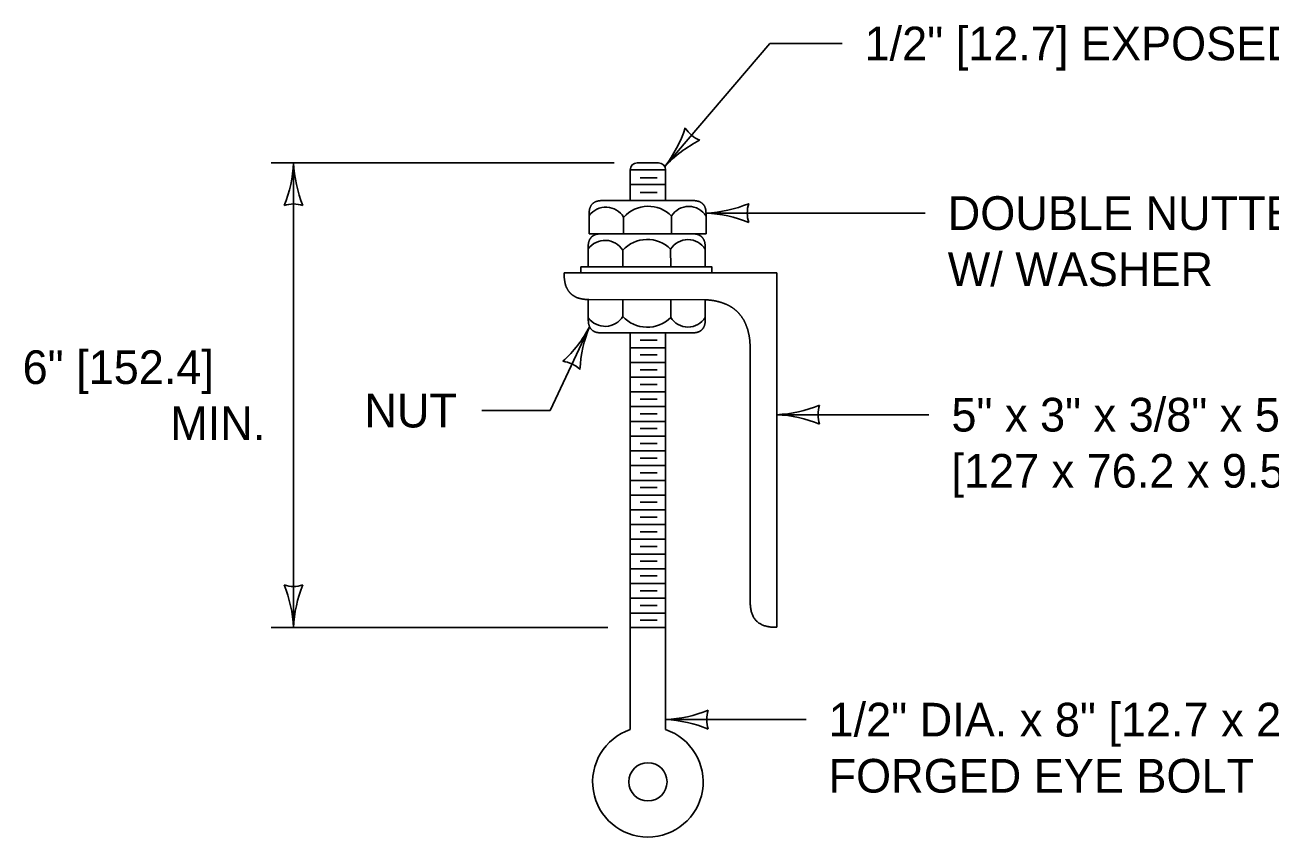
# Model space of a CAD drawing. Extents: x 49991.4 to 50021, y 49987.6 to 50011.4.
# Drawn here: x 50013.253 to 50015.471, y 49992.082 to 49993.529 of the extents above; entities that cross this region are included whole.
import ezdxf

# ---------------------------------------------------------------- set-up
doc = ezdxf.new("R2010")
doc.units = 0
for name, color, linetype in [('Level 1', 7, 'Continuous'), ('Level 2', 7, 'Continuous'), ('Level 3', 7, 'Continuous')]:
    doc.layers.add(name, color=color, linetype=linetype)

msp = doc.modelspace()

# ---------------------------------------------------------------- linework, layer by layer
at = {"layer": 'Level 1'}
for p, q in [((50014.3313, 49993.2711), (50014.3313, 49993.2166)), ((50014.3313, 49993.2711), (50014.3943, 49993.2711)), ((50014.3439, 49993.2837), (50014.3817, 49993.2837)), ((50014.3943, 49993.2711), (50014.3943, 49993.2166)), ((50014.3313, 49993.245), (50014.3943, 49993.245)), ((50014.349, 49993.2573), (50014.379, 49993.2573)), ((50014.349, 49993.2311), (50014.379, 49993.2311)), ((50014.443, 49993.2166), (50014.2815, 49993.2166)), ((50014.2582, 49993.1932), (50014.2582, 49993.1573)), ((50014.3196, 49993.1871), (50014.3196, 49993.1573)), ((50014.4049, 49993.1573), (50014.4049, 49993.189)), ((50014.4664, 49993.1573), (50014.4664, 49993.1932)), ((50014.2582, 49993.1573), (50014.4664, 49993.1573)), ((50014.4414, 49993.1573), (50014.2798, 49993.1573)), ((50014.2566, 49993.134), (50014.2566, 49993.0984)), ((50014.4034, 49993.0984), (50014.4033, 49993.1299)), ((50014.4648, 49993.0984), (50014.4648, 49993.134)), ((50014.318, 49993.1279), (50014.318, 49993.0984)), ((50014.5924, 49993.0875), (50014.2137, 49993.0875)), ((50014.2137, 49993.0875), (50014.2137, 49993.0847)), ((50014.5924, 49992.4563), (50014.5924, 49993.0875)), ((50014.2566, 49993.04), (50014.4649, 49993.0398)), ((50014.2566, 49993.0042), (50014.2566, 49993.04)), ((50014.3181, 49993.0101), (50014.3183, 49993.04)), ((50014.4034, 49993.0399), (50014.4034, 49993.0082)), ((50014.4649, 49993.0398), (50014.4649, 49993.0042)), ((50014.4416, 49992.9806), (50014.28, 49992.9806)), ((50014.3313, 49992.9806), (50014.3313, 49992.274)), ((50014.3313, 49992.9806), (50014.3943, 49992.9806)), ((50014.3943, 49992.9806), (50014.3943, 49992.2741)), ((50014.3313, 49992.9543), (50014.3943, 49992.9543)), ((50014.349, 49992.9678), (50014.379, 49992.9678)), ((50014.349, 49992.9415), (50014.379, 49992.9415)), ((50014.545, 49992.9509), (50014.545, 49992.501)), ((50014.3313, 49992.9282), (50014.3943, 49992.9282)), ((50014.349, 49992.9152), (50014.379, 49992.9152)), ((50014.3313, 49992.9019), (50014.3943, 49992.9019)), ((50014.349, 49992.889), (50014.379, 49992.889)), ((50014.3313, 49992.8756), (50014.3943, 49992.8756)), ((50014.3313, 49992.8494), (50014.3943, 49992.8494)), ((50014.349, 49992.8627), (50014.379, 49992.8627)), ((50014.3313, 49992.8231), (50014.3943, 49992.8231)), ((50014.349, 49992.8365), (50014.379, 49992.8365)), ((50014.3313, 49992.7968), (50014.3943, 49992.7968)), ((50014.349, 49992.8103), (50014.379, 49992.8103)), ((50014.349, 49992.7839), (50014.379, 49992.7839)), ((50014.3313, 49992.7707), (50014.3943, 49992.7707)), ((50014.349, 49992.7577), (50014.379, 49992.7577)), ((50014.3313, 49992.7443), (50014.3943, 49992.7443)), ((50014.349, 49992.7315), (50014.379, 49992.7315)), ((50014.3313, 49992.718), (50014.3943, 49992.718)), ((50014.3313, 49992.6919), (50014.3943, 49992.6919)), ((50014.349, 49992.7052), (50014.379, 49992.7052)), ((50014.3313, 49992.6656), (50014.3943, 49992.6656)), ((50014.349, 49992.6789), (50014.379, 49992.6789)), ((50014.349, 49992.6527), (50014.379, 49992.6527)), ((50014.3313, 49992.6393), (50014.3943, 49992.6393)), ((50014.349, 49992.6264), (50014.379, 49992.6264)), ((50014.3313, 49992.6131), (50014.3943, 49992.6131)), ((50014.349, 49992.6002), (50014.379, 49992.6002)), ((50014.3313, 49992.5868), (50014.3943, 49992.5868)), ((50014.3313, 49992.5605), (50014.3943, 49992.5605)), ((50014.349, 49992.574), (50014.379, 49992.574)), ((50014.3313, 49992.5344), (50014.3943, 49992.5344)), ((50014.349, 49992.5477), (50014.379, 49992.5477)), ((50014.3313, 49992.5081), (50014.3943, 49992.5081)), ((50014.349, 49992.5214), (50014.379, 49992.5214)), ((50014.349, 49992.4952), (50014.379, 49992.4952)), ((50014.3313, 49992.4817), (50014.3943, 49992.4817)), ((50014.349, 49992.4689), (50014.379, 49992.4689)), ((50014.3313, 49992.4556), (50014.3943, 49992.4556)), ((50014.5924, 49992.4563), (50014.5898, 49992.4563))]:
    msp.add_line(p, q, dxfattribs=at)
msp.add_lwpolyline([(50014.4769, 49993.0875), (50014.4769, 49993.0984), (50014.2436, 49993.0984), (50014.2436, 49993.0875)], dxfattribs=at)
msp.add_circle((50014.3628, 49992.1809), 0.0341, dxfattribs=at)
for centre, radius, start, end in [((50014.3439, 49993.2711), 0.0126, 90, 180), ((50014.3817, 49993.2711), 0.0126, 0, 90), ((50014.288, 49993.1679), 0.0369, 31.3232, 143.8567), ((50014.3632, 49993.1477), 0.0587, 44.7321, 137.9001), ((50014.4356, 49993.1698), 0.0362, 31.6559, 147.9066), ((50014.2864, 49993.1087), 0.0369, 31.3232, 143.832), ((50014.3615, 49993.0886), 0.0587, 44.7321, 137.9001), ((50014.434, 49993.1107), 0.0362, 31.6277, 147.9066), ((50014.2866, 49993.0293), 0.0369, 215.7511, 328.6768), ((50014.3617, 49993.0495), 0.0587, 222.0999, 315.2679), ((50014.4341, 49993.0274), 0.0362, 212.0934, 328.1984), ((50014.3628, 49992.1808), 0.0984, 108.672, 71.33)]:
    msp.add_arc(centre, radius, start, end, dxfattribs=at)
for points in [[(50014.2582, 49993.1932), (50014.2582, 49993.1943), (50014.2582, 49993.1956), (50014.2583, 49993.1969), (50014.2584, 49993.198), (50014.2587, 49993.1992), (50014.2588, 49993.2003), (50014.2588, 49993.2013), (50014.2593, 49993.2023), (50014.2596, 49993.2032), (50014.26, 49993.2043), (50014.2603, 49993.2054), (50014.2607, 49993.2061), (50014.2611, 49993.207), (50014.2617, 49993.2078), (50014.2622, 49993.2087), (50014.2627, 49993.2094), (50014.2634, 49993.21), (50014.264, 49993.2106), (50014.2647, 49993.2114), (50014.2654, 49993.2119), (50014.2661, 49993.2124), (50014.2668, 49993.213), (50014.2678, 49993.2135), (50014.2685, 49993.2139), (50014.2694, 49993.2145), (50014.2703, 49993.2147), (50014.2713, 49993.2151), (50014.2723, 49993.2155), (50014.2734, 49993.2156), (50014.2744, 49993.2159), (50014.2756, 49993.2161), (50014.2767, 49993.2162), (50014.2779, 49993.2163), (50014.2791, 49993.2164), (50014.2802, 49993.2166), (50014.2815, 49993.2166)], [(50014.4664, 49993.1932), (50014.4664, 49993.1943), (50014.4662, 49993.1956), (50014.4662, 49993.1969), (50014.4662, 49993.198), (50014.4659, 49993.1992), (50014.4657, 49993.2003), (50014.4655, 49993.2013), (50014.4653, 49993.2023), (50014.4649, 49993.2032), (50014.4646, 49993.2043), (50014.4641, 49993.2054), (50014.4639, 49993.2061), (50014.4634, 49993.207), (50014.4629, 49993.2078), (50014.4623, 49993.2087), (50014.4617, 49993.2094), (50014.4612, 49993.21), (50014.4605, 49993.2106), (50014.4599, 49993.2114), (50014.4592, 49993.2119), (50014.4585, 49993.2124), (50014.4577, 49993.213), (50014.4569, 49993.2135), (50014.456, 49993.2139), (50014.4551, 49993.2145), (50014.4542, 49993.2147), (50014.4532, 49993.2151), (50014.4522, 49993.2155), (50014.4511, 49993.2156), (50014.4501, 49993.2159), (50014.449, 49993.2161), (50014.4478, 49993.2162), (50014.4468, 49993.2163), (50014.4454, 49993.2164), (50014.4442, 49993.2166), (50014.443, 49993.2166)], [(50014.2566, 49993.134), (50014.2566, 49993.1352), (50014.2566, 49993.1364), (50014.2566, 49993.1377), (50014.2567, 49993.1388), (50014.2571, 49993.1399), (50014.2572, 49993.141), (50014.2574, 49993.1422), (50014.2577, 49993.1432), (50014.2579, 49993.1442), (50014.2583, 49993.1453), (50014.2587, 49993.1461), (50014.259, 49993.147), (50014.2596, 49993.1478), (50014.26, 49993.1487), (50014.2606, 49993.1494), (50014.2611, 49993.1502), (50014.2617, 49993.1508), (50014.2625, 49993.1515), (50014.2631, 49993.1522), (50014.2637, 49993.1528), (50014.2645, 49993.1532), (50014.2652, 49993.1538), (50014.2661, 49993.1543), (50014.267, 49993.1548), (50014.2678, 49993.1552), (50014.2688, 49993.1556), (50014.2696, 49993.156), (50014.2708, 49993.1562), (50014.2719, 49993.1566), (50014.2728, 49993.1567), (50014.274, 49993.1569), (50014.2751, 49993.1572), (50014.2762, 49993.1572), (50014.2775, 49993.1573), (50014.2787, 49993.1573), (50014.2798, 49993.1573)], [(50014.4648, 49993.134), (50014.4648, 49993.1352), (50014.4646, 49993.1364), (50014.4646, 49993.1377), (50014.4646, 49993.1388), (50014.4643, 49993.1399), (50014.4641, 49993.141), (50014.4639, 49993.1422), (50014.4637, 49993.1432), (50014.4634, 49993.1442), (50014.463, 49993.1453), (50014.4627, 49993.1461), (50014.4623, 49993.147), (50014.4617, 49993.1478), (50014.4612, 49993.1487), (50014.4607, 49993.1494), (50014.4601, 49993.1502), (50014.4596, 49993.1508), (50014.4589, 49993.1515), (50014.4583, 49993.1522), (50014.4577, 49993.1528), (50014.4569, 49993.1532), (50014.4561, 49993.1538), (50014.4552, 49993.1543), (50014.4544, 49993.1548), (50014.4536, 49993.1552), (50014.4526, 49993.1556), (50014.4516, 49993.156), (50014.4505, 49993.1562), (50014.4495, 49993.1566), (50014.4485, 49993.1567), (50014.4474, 49993.1569), (50014.4463, 49993.1572), (50014.4451, 49993.1572), (50014.4439, 49993.1573), (50014.4427, 49993.1573), (50014.4414, 49993.1573)], [(50014.2566, 49993.0042), (50014.2566, 49993.0029), (50014.2567, 49993.0016), (50014.2569, 49993.0003), (50014.2571, 49992.9992), (50014.2572, 49992.998), (50014.2572, 49992.9969), (50014.2575, 49992.9959), (50014.2578, 49992.995), (50014.2581, 49992.9938), (50014.2585, 49992.9929), (50014.2588, 49992.992), (50014.2593, 49992.9911), (50014.2596, 49992.9903), (50014.2602, 49992.9894), (50014.2608, 49992.9886), (50014.2613, 49992.9878), (50014.2618, 49992.9872), (50014.2626, 49992.9866), (50014.2633, 49992.9859), (50014.2639, 49992.9853), (50014.2646, 49992.9847), (50014.2654, 49992.9842), (50014.2662, 49992.9837), (50014.2672, 49992.9832), (50014.2679, 49992.9829), (50014.2689, 49992.9824), (50014.2699, 49992.9821), (50014.2709, 49992.9818), (50014.2719, 49992.9815), (50014.273, 49992.9814), (50014.2741, 49992.9812), (50014.2752, 49992.9809), (50014.2764, 49992.9809), (50014.2776, 49992.9808), (50014.2788, 49992.9806), (50014.28, 49992.9806)], [(50014.4649, 49993.0042), (50014.4649, 49993.0029), (50014.4648, 49993.0016), (50014.4648, 49993.0003), (50014.4646, 49992.9992), (50014.4646, 49992.998), (50014.4643, 49992.9969), (50014.464, 49992.9959), (50014.4638, 49992.995), (50014.4635, 49992.9938), (50014.4631, 49992.9929), (50014.4628, 49992.992), (50014.4623, 49992.9911), (50014.4619, 49992.9903), (50014.4616, 49992.9894), (50014.4608, 49992.9886), (50014.4602, 49992.9878), (50014.4598, 49992.9872), (50014.4591, 49992.9866), (50014.4585, 49992.9859), (50014.4577, 49992.9853), (50014.457, 49992.9847), (50014.4561, 49992.9842), (50014.4555, 49992.9837), (50014.4546, 49992.9832), (50014.4537, 49992.9829), (50014.4526, 49992.9824), (50014.4518, 49992.9821), (50014.4508, 49992.9818), (50014.4497, 49992.9815), (50014.4486, 49992.9814), (50014.4476, 49992.9812), (50014.4464, 49992.9809), (50014.4453, 49992.9809), (50014.4441, 49992.9808), (50014.4428, 49992.9806), (50014.4416, 49992.9806)], [(50014.545, 49992.501), (50014.5452, 49992.4969), (50014.5455, 49992.4931), (50014.546, 49992.4897), (50014.5466, 49992.4862), (50014.5473, 49992.4829), (50014.5484, 49992.48), (50014.5496, 49992.477), (50014.551, 49992.4743), (50014.5525, 49992.4718), (50014.5542, 49992.4695), (50014.5562, 49992.4674), (50014.5583, 49992.4656), (50014.5606, 49992.4637), (50014.5632, 49992.4623), (50014.5658, 49992.4608), (50014.5687, 49992.4596), (50014.5717, 49992.4586), (50014.575, 49992.4579), (50014.5784, 49992.4572), (50014.5819, 49992.4567), (50014.5857, 49992.4564), (50014.5898, 49992.4563)]]:
    msp.add_spline(points, degree=3, dxfattribs=at)
for points in [[(50014.2137, 49993.0847), (50014.2137, 49993.0834), (50014.2137, 49993.082), (50014.2138, 49993.0807), (50014.2139, 49993.0794), (50014.2139, 49993.0782), (50014.2141, 49993.0769), (50014.2142, 49993.0757), (50014.2144, 49993.0746), (50014.2146, 49993.0734), (50014.2148, 49993.0722), (50014.215, 49993.0711), (50014.2152, 49993.0699), (50014.2153, 49993.0694), (50014.2154, 49993.0688), (50014.2155, 49993.0683), (50014.2156, 49993.068), (50014.2156, 49993.0678), (50014.2157, 49993.0675), (50014.2158, 49993.0672), (50014.2158, 49993.067), (50014.2159, 49993.0667), (50014.216, 49993.0662), (50014.2162, 49993.0657), (50014.2164, 49993.0652), (50014.2166, 49993.0647), (50014.2168, 49993.0642), (50014.217, 49993.0637), (50014.2172, 49993.0632), (50014.2174, 49993.0627), (50014.2176, 49993.0622), (50014.2178, 49993.0618), (50014.2181, 49993.0613), (50014.2183, 49993.0608), (50014.2187, 49993.0599), (50014.2192, 49993.059), (50014.2197, 49993.0581), (50014.2202, 49993.0572), (50014.2206, 49993.0564), (50014.2212, 49993.0556), (50014.2217, 49993.0548), (50014.2223, 49993.0541), (50014.2229, 49993.0534), (50014.2235, 49993.0526), (50014.2241, 49993.0519), (50014.2248, 49993.0512), (50014.2255, 49993.0505), (50014.2262, 49993.0499), (50014.227, 49993.0493), (50014.2278, 49993.0487), (50014.2285, 49993.0481), (50014.2293, 49993.0476), (50014.2301, 49993.0471), (50014.231, 49993.0466), (50014.2318, 49993.0461), (50014.2327, 49993.0456), (50014.2335, 49993.0451), (50014.2344, 49993.0446), (50014.2353, 49993.0441), (50014.2363, 49993.0436), (50014.2373, 49993.0433), (50014.2383, 49993.043), (50014.2394, 49993.0427), (50014.2404, 49993.0424), (50014.2415, 49993.0421), (50014.2425, 49993.0418), (50014.2436, 49993.0416), (50014.2447, 49993.0414), (50014.2459, 49993.0412), (50014.247, 49993.041), (50014.2482, 49993.0408), (50014.2494, 49993.0406), (50014.2506, 49993.0405), (50014.2518, 49993.0404), (50014.2531, 49993.0403), (50014.2543, 49993.0402), (50014.2554, 49993.0401), (50014.2566, 49993.04), (50014.2577, 49993.04)], [(50014.4649, 49993.0398), (50014.4659, 49993.0398), (50014.467, 49993.0397), (50014.468, 49993.0396), (50014.4693, 49993.0395), (50014.4707, 49993.0394), (50014.472, 49993.0393), (50014.4733, 49993.0392), (50014.4745, 49993.039), (50014.4758, 49993.0388), (50014.477, 49993.0386), (50014.4782, 49993.0385), (50014.4794, 49993.0383), (50014.4806, 49993.0381), (50014.4819, 49993.0379), (50014.4831, 49993.0376), (50014.4843, 49993.0373), (50014.4854, 49993.0371), (50014.4866, 49993.0368), (50014.4877, 49993.0366), (50014.4888, 49993.0364), (50014.4899, 49993.0361), (50014.4911, 49993.0358), (50014.4922, 49993.0354), (50014.4933, 49993.035), (50014.4944, 49993.0346), (50014.4954, 49993.0343), (50014.4965, 49993.0339), (50014.4975, 49993.0335), (50014.4985, 49993.0332), (50014.4995, 49993.0328), (50014.5005, 49993.0324), (50014.5015, 49993.0319), (50014.5025, 49993.0315), (50014.5035, 49993.0311), (50014.5044, 49993.0306), (50014.5054, 49993.0302), (50014.5064, 49993.0298), (50014.5073, 49993.0292), (50014.5082, 49993.0287), (50014.5091, 49993.0282), (50014.51, 49993.0276), (50014.5109, 49993.0271), (50014.5117, 49993.0266), (50014.5126, 49993.026), (50014.5134, 49993.0255), (50014.5143, 49993.0249), (50014.5151, 49993.0243), (50014.5159, 49993.0237), (50014.5167, 49993.0231), (50014.5175, 49993.0224), (50014.5183, 49993.0217), (50014.5191, 49993.0211), (50014.5199, 49993.0205), (50014.5206, 49993.0199), (50014.5214, 49993.0193), (50014.5221, 49993.0185), (50014.5228, 49993.0178), (50014.5235, 49993.017), (50014.5242, 49993.0163), (50014.5249, 49993.0155), (50014.5255, 49993.0148), (50014.5262, 49993.014), (50014.5268, 49993.0133), (50014.5274, 49993.0126), (50014.528, 49993.0118), (50014.5286, 49993.011), (50014.5292, 49993.0101), (50014.5298, 49993.0093), (50014.5304, 49993.0084), (50014.5309, 49993.0076), (50014.5315, 49993.0067), (50014.532, 49993.0059), (50014.5326, 49993.005), (50014.5332, 49993.0042), (50014.5337, 49993.0033), (50014.5342, 49993.0023), (50014.5346, 49993.0014), (50014.5351, 49993.0004), (50014.5356, 49992.9994), (50014.536, 49992.9985), (50014.5365, 49992.9975), (50014.537, 49992.9965), (50014.5373, 49992.9955), (50014.5377, 49992.9945), (50014.5381, 49992.9935), (50014.5384, 49992.9925), (50014.5388, 49992.9915), (50014.5392, 49992.9904), (50014.5396, 49992.9894), (50014.54, 49992.9883), (50014.5404, 49992.9872), (50014.5407, 49992.986), (50014.541, 49992.9849), (50014.5413, 49992.9838), (50014.5415, 49992.9827), (50014.5418, 49992.9816), (50014.5421, 49992.9804), (50014.5423, 49992.9793), (50014.5426, 49992.9781), (50014.5429, 49992.9769), (50014.5431, 49992.9756), (50014.5433, 49992.9744), (50014.5435, 49992.9732), (50014.5436, 49992.9719), (50014.5438, 49992.9707), (50014.544, 49992.9695), (50014.5441, 49992.9682), (50014.5443, 49992.967), (50014.5444, 49992.9664), (50014.5444, 49992.9657), (50014.5444, 49992.9651), (50014.5444, 49992.9647), (50014.5444, 49992.9644), (50014.5445, 49992.9641), (50014.5445, 49992.9637), (50014.5445, 49992.9634), (50014.5445, 49992.9631), (50014.5446, 49992.9624), (50014.5446, 49992.9618), (50014.5447, 49992.9612), (50014.5448, 49992.9608), (50014.5448, 49992.9605), (50014.5448, 49992.9602), (50014.5449, 49992.9599), (50014.5449, 49992.9595), (50014.5449, 49992.9592), (50014.545, 49992.9578), (50014.545, 49992.9564), (50014.545, 49992.955), (50014.545, 49992.9536), (50014.545, 49992.9523), (50014.545, 49992.9509)]]:
    msp.add_open_spline(points, degree=3, dxfattribs=at)
at = {"layer": 'Level 3'}
for p, q in [((50014.5801, 49993.4963), (50014.3928, 49993.2771)), ((50014.7087, 49993.4963), (50014.5801, 49993.4963)), ((50014.303, 49993.2838), (50013.6916, 49993.2838)), ((50013.7316, 49993.2838), (50013.7316, 49992.4556)), ((50014.8568, 49993.1942), (50014.4664, 49993.1942)), ((50014.1887, 49992.8423), (50014.2587, 49992.9914)), ((50014.1887, 49992.8423), (50014.0669, 49992.8423)), ((50014.8634, 49992.835), (50014.5924, 49992.835)), ((50014.2913, 49992.4556), (50013.6916, 49992.4556)), ((50014.6445, 49992.2917), (50014.3943, 49992.2917))]:
    msp.add_line(p, q, dxfattribs=at)
for centre, radius, start, end in [((50014.2084, 49993.4195), 0.233, 322.3201, 341.57), ((50014.4761, 49993.3745), 0.0548, 211.6316, 247.354), ((50014.5557, 49993.1258), 0.2223, 116.9488, 137.1323), ((50013.5095, 49993.293), 0.2223, 337.456, 357.6395), ((50013.9643, 49993.2953), 0.233, 182.8273, 202.0772), ((50013.7316, 49993.1556), 0.0548, 72.1388, 107.8612), ((50014.4549, 49993.4269), 0.233, 272.8273, 292.0772), ((50014.5946, 49993.1942), 0.0548, 162.1388, 197.8612), ((50014.4572, 49992.9721), 0.2223, 67.456, 87.6395), ((50014.0617, 49993.0945), 0.2223, 312.3218, 332.5053), ((50014.4744, 49992.9034), 0.233, 157.6931, 176.9429), ((50014.2044, 49992.8758), 0.0548, 47.0046, 82.7269), ((50014.5809, 49993.0677), 0.233, 272.8273, 292.0772), ((50014.7206, 49992.835), 0.0548, 162.1388, 197.8612), ((50014.5832, 49992.6129), 0.2223, 67.456, 87.6395), ((50013.7316, 49992.5838), 0.0548, 252.1388, 287.8612), ((50013.4989, 49992.4441), 0.233, 2.8273, 22.0772), ((50013.9537, 49992.4464), 0.2223, 157.456, 177.6395), ((50014.3828, 49992.5244), 0.233, 272.8273, 292.0772), ((50014.5225, 49992.2917), 0.0548, 162.1388, 197.8612), ((50014.3851, 49992.0696), 0.2223, 67.456, 87.6395)]:
    msp.add_arc(centre, radius, start, end, dxfattribs=at)

# ---------------------------------------------------------------- texts
at = {"layer": 'Level 2'}
for s, p in [('1/2" [12.7] EXPOSED THREADS', (50014.7487, 49993.4663)), ('DOUBLE NUTTED', (50014.8968, 49993.1642)), ('W/ WASHER', (50014.8968, 49993.0642)), ('6" [152.4]', (50013.2491, 49992.8897)), ('NUT', (50013.8579, 49992.8123)), ('5" x 3" x 3/8" x 5" L', (50014.9034, 49992.805)), ('MIN.', (50013.512, 49992.7897)), ('[127 x 76.2 x 9.525 x 127 L]', (50014.9034, 49992.705)), ('1/2" DIA. x 8" [12.7 x 203.2] DROP', (50014.6845, 49992.2617)), ('FORGED EYE BOLT', (50014.6845, 49992.1617))]:
    msp.add_text(s, height=0.06, dxfattribs=at).set_placement(p)

doc.saveas('drawing.dxf')
